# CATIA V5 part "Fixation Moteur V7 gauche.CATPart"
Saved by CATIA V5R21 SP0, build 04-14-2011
Part number: MOTEURGAUCHE
Bounding box of the stored display mesh (mm): x -4.2 to 4.2, y -40 to 0, z -20 to 40
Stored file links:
  C:\Users\2027.DESARCY-LEMIE30\Desktop\V14(17.02.2023)\Fixation Moteur V7 gauche.CATPart
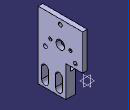
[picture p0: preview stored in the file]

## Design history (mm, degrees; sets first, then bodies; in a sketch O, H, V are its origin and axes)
Body1 (main body)
  Sketch1 on yz-plane, origin (0, 0, 0), H (0, 1, 0), V (0, 0, 1)
    line L1 (-40, 40) -> (0, 40)
    line L2 (0, 40) -> (0, 0)
    line L3 (0, 0) -> (-40, 0)
    line L4 (-40, 0) -> (-40, 40)
    point P3 (0, 0)
    length L4 = 40
    length L1 = 40
    horizontal: L1 H, L3 H
    vertical: L2 V, L4 V
    coincidence: P3 O
  Pad1: profile Sketch1, direction (1, 0, 0), length 4.2
  Sketch2 on end face of Pad1, origin (4.2, 0, 0), H (0, 1, 0), V (0, 0, 1)
    point P1 (-40, 0)
    line L1 (-40, 0) -> (-15, 0)
    line L2 (-15, 0) -> (-15, -20)
    line L3 (-15, -20) -> (-40, -20)
    line L4 (-40, -20) -> (-40, 0)
    reference projected point E1 (-40, 0) from vertex [face of Pad1 from Sketch1.L3 | end face of Pad1 | face of Pad1 from Sketch1.L4]
    length L2 = 20
    length L3 = 25
    horizontal: L1 H, L3 H
    vertical: L2 V, L4 V
    coincidence: P1 E1
  Pad2: profile Sketch2, direction (-1, 0, 0), length 8.4
  Sketch3 on end face of Pad2, origin (-4.2, 0, 0), H (0, -1, 0), V (0, 0, 1)
    point P1 (18.15, -5)
    line L1 (24.35, -5) -> (24.35, -15)
    line L2 (18.15, -15) -> (18.15, -5)
    point P2 (24.35, -5)
    point P3 (24.35, -15)
    point P4 (18.15, -15)
    axis line L3 (27.5, 2.3624) -> (27.5, -21.6714)
    reference projected line E1 (40, 0) -> (40, -20) from edge [end face of Pad2 | face of Pad2 from Sketch2.L4]
    arc A1 centre (21.25, -5) radius 3.1 from (24.35, -5) to (18.15, -5) ccw
    point P8 (10.7649, -15.4491)
    arc A2 centre (21.25, -15) radius 3.1 from (18.15, -15) to (24.35, -15) ccw
    point P9 (21.25, -15)
    point P10 (18.15, -15)
    point P11 (24.35, -15)
    point P12 (36.85, -5)
    point P13 (36.85, -15)
    line L4 (36.85, -15) -> (36.85, -5)
    point P14 (30.65, -5)
    arc A3 centre (33.75, -5) radius 3.1 from (30.65, -5) to (36.85, -5) cw
    point P16 (30.65, -15)
    line L5 (30.65, -5) -> (30.65, -15)
    point P17 (30.65, -15)
    point P18 (36.85, -15)
    point P19 (33.75, -15)
    arc A4 centre (33.75, -15) radius 3.1 from (36.85, -15) to (30.65, -15) cw
    reference projected line E2 (40, -20) -> (15, -20) from edge [end face of Pad2 | face of Pad2 from Sketch2.L3]
    distance L3 E1 = 12.5
    radius A1 = 3.1
    distance P9 P19 = 12.5
    length L4 = 10
    distance A4 E2 = 1.9
    vertical: L1 V, L2 V, L3 V
    tangency: A1 L1, A1 L2, A2 L1, A2 L2
    coincidence: P4 A2, L1 P11, L2 P10, P3 P11, P4 P10, P13 P18, P16 P17
    symmetry: P1 P12 L3, P4 P13 L3, L2 L4 L3, P2 P14 L3, A1 A3 L3, P3 P16 L3, L1 L5 L3, P11 P17 L3, P10 P18 L3, A2 A4 L3
  Pocket1: profile Sketch3, direction (1, 0, 0), through (limit type 3)
  Sketch4 on start face of Pad1, origin (0, 0, 0), H (0, -1, 0), V (0, 0, 1)
    construction line L1 (0, 20) -> (40, 20)
    point P1 (0, 20)
    point P2 (40, 20)
    reference projected line E1 (0, 40) -> (40, 40) from edge [start face of Pad1 | face of Pad1 from Sketch1.L1]
    reference projected line E2 (0, 0) -> (0, 40) from edge [start face of Pad1 | face of Pad2]
    reference projected line E3 (40, 40) -> (40, 0) from edge [start face of Pad1 | face of Pad1 from Sketch1.L4]
    construction line L2 (20, 40) -> (20, 0)
    point P3 (20, 40)
    point P4 (20, 0)
    reference projected line E4 (0, 40) -> (40, 40) from edge [start face of Pad1 | face of Pad1 from Sketch1.L1]
    reference projected line E5 (40, 0) -> (0, 0) from edge [start face of Pad1 | face of Pad1 from Sketch1.L3]
    reference projected line E6 (40, 40) -> (40, 0) from edge [start face of Pad1 | face of Pad1 from Sketch1.L4]
    circle A1 centre (20, 20) radius 4
    point P5 (20, 20)
    construction line L3 (20, 20) -> (0, 8.453)
    point P6 (0, 8.453)
    axis line L4 (20, 20) -> (40, 8.453)
    point P7 (40, 8.453)
    reference projected line E7 (40, 40) -> (40, 0) from edge [start face of Pad1 | face of Pad1 from Sketch1.L4]
    circle A2 centre (20, 35.5885) radius 1.75
    point P8 (20, 35.5885)
    point P9 (33.5, 12.2058)
    circle A3 centre (33.5, 12.2058) radius 1.75
    point P10 (6.5, 12.2058)
    circle A4 centre (6.5, 12.2058) radius 1.75
    distance E1 L1 = 20
    distance L2 E6 = 20
    radius A1 = 4
    angle L3 L2 = 120
    angle L2 L4 = 120
    radius A2 = 1.75
    distance P9 P10 = 27
    horizontal: L1 H
    coincidence: P1 E2, P2 E3, E4 P3, P4 E5, P5 L2, P6 V, P7 E7, P8 L2
    vertical: L2 V
    midpoint: P5 L2
    symmetry: A2 A3 L3, A3 A4 L2
  Pocket2: profile Sketch4, direction (1, 0, 0), through (limit type 3)
  Sketch5 on start face of Pad1, origin (0, -33.6663, 26.8229), H (0, 1, 0), V (0, 0, -1)
    point P1 (22.6663, 6.8229)
    axis line L1 (13.6663, 6.8229) -> (56.6573, 6.8229)
    point P2 (13.6663, 6.8229)
    reference projected circle E1 centre (13.6663, 6.8229) radius 4 from edge [start face of Pad1 | face of Pocket2 from Sketch4.A1]
    distance P2 P1 = 9
    horizontal: L1 H
    concentricity: P2 E1
    coincidence: P1 L1
  Hole1: placed by Sketch5, at (0, -11, 20) direction (1, 0, 0), diameter 3, through (limit type 6), counterbore diameter 6, counterbore depth 3
  RectPattern1: of Hole1, direction 1 instances 2, spacing 18, along face of Pad1 from Sketch1.L1 reversed
  Sketch6 on start face of Pad1, origin (0, 0, 0), H (0, -1, 0), V (0, 0, 1)
    line L1 (0, 0) -> (15, 0)
    line L2 (15, 0) -> (15, 8)
    line L3 (15, 8) -> (0, 8)
    line L4 (0, 8) -> (0, 0)
    reference projected line E1 (15, -20) -> (15, 0) from edge [end face of Pad2 | face of Pad2 from Sketch2.L2]
    length L2 = 8
    horizontal: L1 H, L3 H
    vertical: L2 V, L4 V
    coincidence: L2 E1
  Pocket3: profile Sketch6, direction (1, 0, 0), through (limit type 3)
